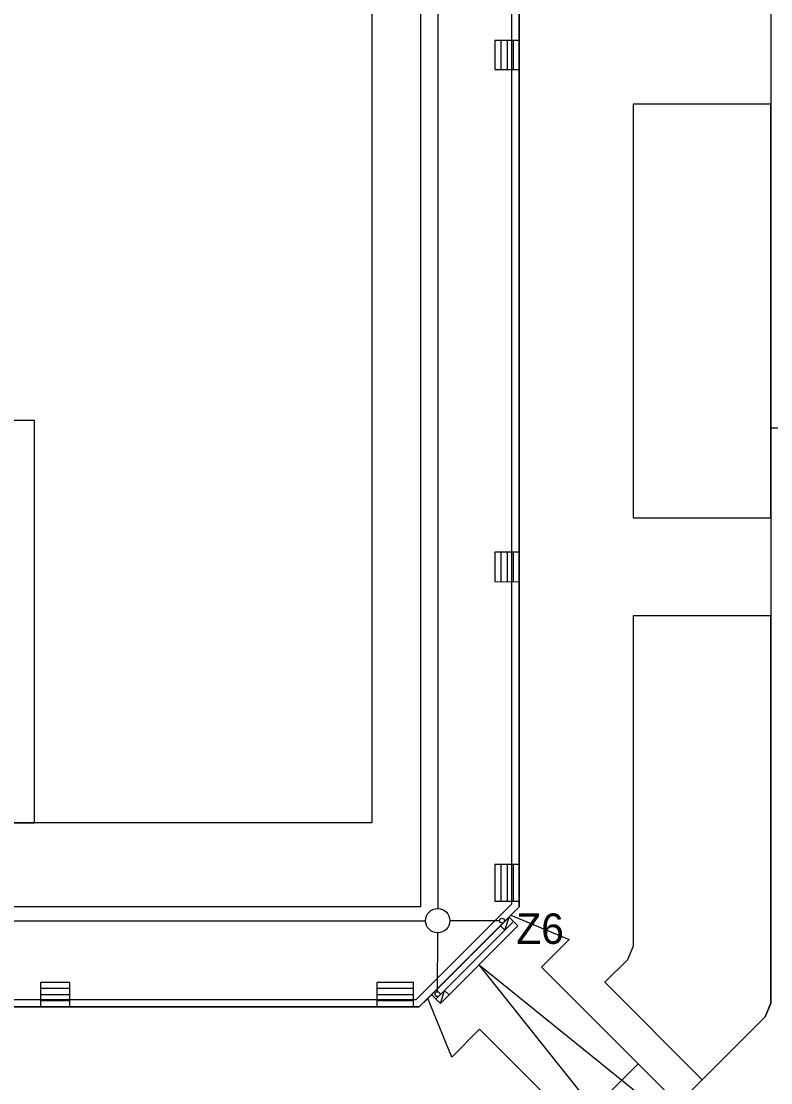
# Model space of a CAD drawing. Extents: x -263964 to -263544, y -1242317 to -1242020.
# Drawn here: x -263832.36 to -263801.59, y -1242227.54 to -1242184 of the extents above; entities that cross this region are included whole.
import ezdxf

# ---------------------------------------------------------------- set-up
doc = ezdxf.new("R2010")
doc.units = 0
doc.layers.add('KFA_KOORDINACNA_SITUACIA_DSP_SEDA', color=7, linetype='Continuous')

msp = doc.modelspace()

# ---------------------------------------------------------------- linework, layer by layer
at = {"layer": 'KFA_KOORDINACNA_SITUACIA_DSP_SEDA'}
for p, q in [((-263815.263, -1242164.687), (-263815.263, -1242220.396)), ((-263811.918, -1242184.782), (-263812.918, -1242184.782)), ((-263812.918, -1242184.782), (-263812.918, -1242185.982)), ((-263812.668, -1242184.782), (-263812.668, -1242185.982)), ((-263812.418, -1242184.782), (-263812.418, -1242185.982)), ((-263812.168, -1242184.782), (-263812.168, -1242185.982)), ((-263812.918, -1242185.982), (-263811.918, -1242185.982)), ((-263807.243, -1242187.394), (-263807.243, -1242204.369)), ((-263801.593, -1242187.394), (-263807.243, -1242187.394)), ((-263801.593, -1242204.369), (-263801.593, -1242187.394)), ((-263801.593, -1242200.682), (-263800.593, -1242200.682)), ((-263807.243, -1242204.369), (-263801.593, -1242204.369)), ((-263811.924, -1242205.773), (-263812.918, -1242205.782)), ((-263812.918, -1242205.782), (-263812.918, -1242206.982)), ((-263812.668, -1242205.782), (-263812.668, -1242206.982)), ((-263812.418, -1242205.782), (-263812.418, -1242206.982)), ((-263812.168, -1242205.782), (-263812.168, -1242206.982)), ((-263812.918, -1242206.982), (-263811.924, -1242206.991)), ((-263807.243, -1242208.394), (-263807.243, -1242221.942)), ((-263801.593, -1242208.394), (-263807.243, -1242208.394)), ((-263801.593, -1242224.282), (-263801.593, -1242208.394)), ((-263811.939, -1242218.592), (-263812.918, -1242218.592)), ((-263812.918, -1242218.592), (-263812.918, -1242220.092)), ((-263812.668, -1242218.592), (-263812.668, -1242220.092)), ((-263812.418, -1242218.592), (-263812.418, -1242220.092)), ((-263812.168, -1242218.592), (-263812.168, -1242220.092)), ((-263812.918, -1242220.092), (-263811.918, -1242220.092)), ((-263815.516, -1242223.929), (-263812.335, -1242220.747)), ((-263812.506, -1242221.283), (-263812.335, -1242220.747)), ((-263812.151, -1242220.931), (-263812.335, -1242220.747)), ((-263851.668, -1242220.896), (-263815.763, -1242220.896)), ((-263815.334, -1242224.112), (-263812.152, -1242220.929)), ((-263811.968, -1242221.113), (-263815.15, -1242224.295)), ((-263812.725, -1242220.896), (-263814.763, -1242220.896)), ((-263812.504, -1242221.284), (-263812.688, -1242221.101)), ((-263811.968, -1242221.113), (-263812.152, -1242220.929)), ((-263815.27, -1242223.809), (-263815.264, -1242221.396)), ((-263807.243, -1242221.942), (-263807.472, -1242222.496)), ((-263807.472, -1242222.496), (-263808.4, -1242223.424)), ((-263830.369, -1242223.432), (-263831.567, -1242223.432)), ((-263831.567, -1242223.432), (-263831.567, -1242224.432)), ((-263830.369, -1242223.682), (-263831.567, -1242223.682)), ((-263830.369, -1242224.432), (-263830.369, -1242223.432)), ((-263816.259, -1242223.432), (-263817.757, -1242223.432)), ((-263817.757, -1242223.432), (-263817.757, -1242224.432)), ((-263816.259, -1242223.682), (-263817.757, -1242223.682)), ((-263816.259, -1242224.432), (-263816.259, -1242223.432)), ((-263815.15, -1242224.295), (-263814.98, -1242223.758)), ((-263814.797, -1242223.942), (-263814.98, -1242223.758)), ((-263808.4, -1242223.424), (-263804.405, -1242227.419)), ((-263830.369, -1242223.932), (-263831.567, -1242223.932)), ((-263830.369, -1242224.182), (-263831.567, -1242224.182)), ((-263816.259, -1242223.932), (-263817.757, -1242223.932)), ((-263816.259, -1242224.182), (-263817.757, -1242224.182)), ((-263815.333, -1242224.113), (-263815.516, -1242223.929)), ((-263815.15, -1242224.295), (-263815.334, -1242224.112)), ((-263801.822, -1242224.837), (-263801.593, -1242224.282)), ((-263804.405, -1242227.419), (-263801.822, -1242224.837))]:
    msp.add_line(p, q, dxfattribs=at)
for points in [[(-263909.043, -1242125.432), (-263902.343, -1242125.432), (-263902.343, -1242104.482), (-263902.112, -1242103.927), (-263898.54, -1242100.355), (-263895.995, -1242097.81), (-263892.423, -1242094.238), (-263891.868, -1242094.007), (-263812.071, -1242094.007), (-263811.513, -1242094.238), (-263801.823, -1242103.927), (-263801.593, -1242104.482), (-263801.593, -1242224.282), (-263801.824, -1242224.838), (-263805.392, -1242228.407)], [(-263811.918, -1242108.434), (-263811.918, -1242220.33), (-263812.262, -1242220.675), (-263809.862, -1242221.669), (-263810.999, -1242222.806), (-263807.039, -1242226.765), (-263809.585, -1242229.311), (-263813.545, -1242225.351), (-263814.681, -1242226.488), (-263815.675, -1242224.088), (-263816.02, -1242224.432), (-263887.916, -1242224.432)], [(-263807.941, -1242230.956), (-263813.544, -1242225.352), (-263814.681, -1242226.488), (-263815.675, -1242224.088), (-263812.262, -1242220.675)], [(-263812.262, -1242220.675), (-263809.863, -1242221.669), (-263810.999, -1242222.806), (-263805.392, -1242228.407)], [(-263803.204, -1242235.693), (-263813.559, -1242222.704), (-263800.652, -1242233.141)]]:
    msp.add_lwpolyline(points, dxfattribs=at)
for points in [[(-263816.02, -1242224.432), (-263811.918, -1242220.33), (-263811.918, -1242108.434), (-263816.02, -1242104.332), (-263887.916, -1242104.332), (-263892.018, -1242108.434), (-263892.018, -1242147.332), (-263893.618, -1242147.332), (-263893.618, -1242162.382), (-263894.718, -1242162.382), (-263894.718, -1242166.382), (-263893.618, -1242166.382), (-263893.618, -1242181.432), (-263892.018, -1242181.432), (-263892.018, -1242220.33), (-263887.916, -1242224.432)], [(-263816.144, -1242224.132), (-263812.218, -1242220.206), (-263812.218, -1242108.558), (-263816.144, -1242104.632), (-263887.792, -1242104.632), (-263891.718, -1242108.558), (-263891.718, -1242147.632), (-263893.318, -1242147.632), (-263893.318, -1242162.682), (-263894.418, -1242162.682), (-263894.418, -1242166.082), (-263893.318, -1242166.082), (-263893.318, -1242181.132), (-263891.718, -1242181.132), (-263891.718, -1242220.206), (-263887.792, -1242224.132)], [(-263887.968, -1242108.434), (-263815.968, -1242108.434), (-263815.968, -1242220.33), (-263887.968, -1242220.33)], [(-263885.968, -1242111.882), (-263817.968, -1242111.882), (-263817.968, -1242216.882), (-263885.968, -1242216.882)], [(-263801.593, -1242187.394), (-263807.243, -1242187.394), (-263807.243, -1242204.369), (-263801.593, -1242204.369)], [(-263831.808, -1242200.382), (-263872.128, -1242200.382), (-263872.128, -1242216.882), (-263831.808, -1242216.882)], [(-263801.593, -1242208.394), (-263807.243, -1242208.394), (-263807.243, -1242221.942), (-263807.472, -1242222.496), (-263808.4, -1242223.424), (-263804.405, -1242227.419), (-263801.822, -1242224.837), (-263801.593, -1242224.282)], [(-263812.688, -1242221.101), (-263812.506, -1242221.283), (-263812.335, -1242220.747)], [(-263814.98, -1242223.758), (-263815.334, -1242224.112), (-263815.15, -1242224.295)]]:
    msp.add_lwpolyline(points, close=True, dxfattribs=at)
for centre, radius in [((-263815.263, -1242220.896), 0.5), ((-263812.625, -1242220.896), 0.1), ((-263815.27, -1242223.909), 0.1)]:
    msp.add_circle(centre, radius, dxfattribs=at)

# ---------------------------------------------------------------- texts
msp.add_text('Z6', height=1.25, dxfattribs=at).set_placement((-263812.038, -1242221.848))

doc.saveas('drawing.dxf')
